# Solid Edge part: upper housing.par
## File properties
Author: Robert a Rhodes jr
Template: NORMENG.PAR
Last saved by: CADCIM
Revision: 13
Application: Solid Edge
Accuracy: 0.99
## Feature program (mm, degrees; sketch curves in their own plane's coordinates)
sketch for "unnamed Protrusion 1" plane through (0, 0, 0) normal (0, -1, 0) x-axis (1, 0, 0)
  arc centre (0, 0) radius 152.4 from (152.4, 0) to (-152.4, 0) ccw
  line (-152.4, 0) -> (152.4, 0)
extrude "unnamed Protrusion 1" add finite 203.2 symmetric
swept protrusion "SweptProtrusion_1"  Profile_5_Plane_FractionOfCurve = 0
fillet "Round_1" radius 38.1
fillet "Round_2" radius 12.7
thinwall "Thinwall_2"  Thickness = 6.35 mm
sketch for "unnamed Cutout 1" plane through (0, -101.6, 76.2) normal (0, -1, 0) x-axis (1, 0, 0)
  arc centre (0, -76.2) radius 123.825 from (-123.825, -76.2) to (123.825, -76.2) cw
extrude "unnamed Cutout 1" cut through along -normal
sketch for "unnamed Cutout 2" plane through (0, 95.25, 73.025) normal (0, -1, 0) x-axis (1, 0, 0)
  arc centre (0, -73.025) radius 38.1 from (38.1, -73.025) to (-38.1, -73.025) ccw
extrude "unnamed Cutout 2" cut through along -normal
sketch for "ExtrudedProtrusion_2" plane through (0, -101.6, 76.2) normal (0, -1, 0) x-axis (1, 0, 0)
  line (152.4, -76.2) -> (190.5, -76.2)
  line (190.5, -76.2) -> (190.5, -66.04)
  line (190.5, -66.04) -> (152.061, -66.04)
  arc centre (0, -76.2) radius 152.4 from (152.4, -76.2) to (152.061, -66.04) ccw
extrude "ExtrudedProtrusion_2" add finite 203.2 along -normal
mirror "unnamed Mirror 1" of "ExtrudedProtrusion_2" about plane through (0, 0, 0) normal (1, 0, 0)
extrude "unnamed Protrusion 2" add finite 203.2
sketch for "Hole_1" plane through (171.2507, 0, 10.16) normal (0, 0, 1) x-axis (0, 1, 0)
hole "Hole_1" diameter 10.414 through
pattern "unnamed Pattern 1" of "Hole_1"
pattern "unnamed Pattern 2"
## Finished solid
Body 1: solid body, 69 faces, 164 edges, 88 vertices.
  Faces by surface: blend 24, plane 15, cylinder 14, offset 6, spline 6, torus 4
  Edges by curve: circle 60, intersection 56, line 45, curve on surface 3
Bounding box of the edges (mm; curved faces can reach further): 492.760 x 203.200 x 255.273, from (-302.26, -101.6, 0) to (190.5, 101.6, 255.2731).
Cylindrical faces by radius (mm): R5.207 x8, R12.7 x1, R19.05 x1, R38.1 x1, R123.825 x1, R146.05 x1, R152.4 x1
Toroidal faces (ring radius, tube radius in mm): R165.1 r12.7 x2, R165.1 r19.05 x2
Planar faces by outward normal: +x 1, +y 4, +z 2, -x 2, -y 4, -z 2
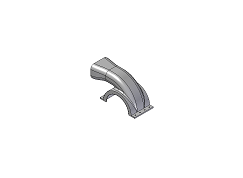
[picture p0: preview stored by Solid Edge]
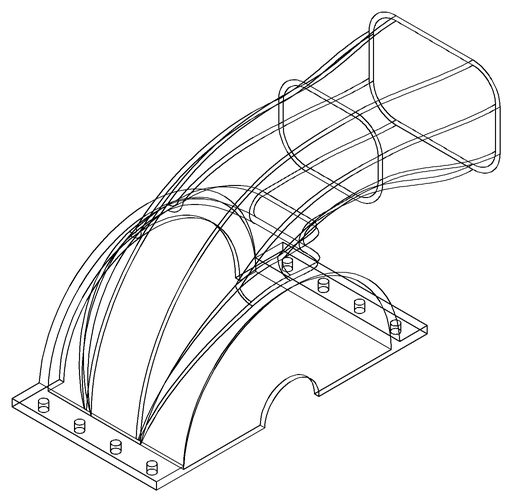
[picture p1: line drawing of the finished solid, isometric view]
